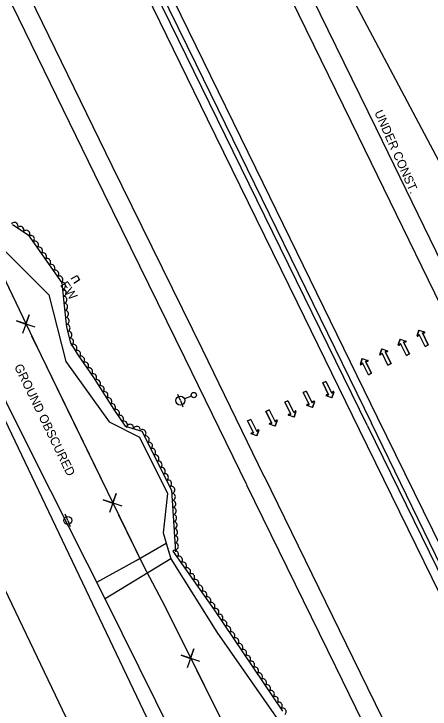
# Model space of a CAD drawing. Extents: x 1746719 to 1766531, y 631721 to 662391.
# Drawn here: x 1763435.4 to 1763670.9, y 634787.8 to 635180.8 of the extents above; entities that cross this region are included whole.
import ezdxf

# ---------------------------------------------------------------- set-up
doc = ezdxf.new("R2010")
doc.units = 0
for name, color, linetype in [('SURVEY - AERIAL SURVEY - Photo Control - Points - Elevations', 7, 'Continuous'), ('SURVEY - AERIAL SURVEY - Photo Control - Points - Locators', 7, 'Continuous'), ('SURVEY - AERIAL SURVEY - Photo Control - Points - Numbers', 7, 'Continuous'), ('SURVEY - AERIAL SURVEY - Photo Control with Text', 7, 'Continuous'), ('SURVEY - CENTERLINE - Existing Roads - Development', 7, 'Continuous'), ('SURVEY - CENTERLINE - Existing Roads Curve Text', 7, 'Continuous'), ('SURVEY - CENTERLINE - Existing Roads Text', 7, 'Continuous'), ('SURVEY - CENTERLINE - Preliminary - Development', 7, 'Continuous')]:
    doc.layers.add(name, color=color, linetype=linetype)

msp = doc.modelspace()

# ---------------------------------------------------------------- linework, layer by layer
at = {"layer": 'SURVEY - AERIAL SURVEY - Photo Control - Points - Elevations'}
for points in [[(1763704.89, 634983.66), (1763640.33, 635116.26), (1763572.67, 635254.52), (1763501.45, 635399.63), (1763427.19, 635551.31), (1763340.37, 635728.58), (1763263.89, 635885.41), (1763187.43, 636041.67), (1763122.68, 636173.79), (1763042.99, 636337.18), (1762975.48, 636475.16), (1762847.24, 636736.51)], [(1763695, 634978.85), (1763630.44, 635111.43), (1763562.79, 635249.68), (1763491.57, 635394.79), (1763417.31, 635546.47), (1763330.49, 635723.75), (1763254.01, 635880.59), (1763177.55, 636036.83), (1763112.8, 636168.96), (1763033.11, 636332.35), (1762965.6, 636470.32), (1762837.37, 636731.67)], [(1763641.05, 634952.58), (1763576.52, 635085.11), (1763508.91, 635223.28), (1763437.7, 635368.38), (1763363.42, 635520.08), (1763276.58, 635697.4), (1763200.09, 635854.25), (1763123.66, 636010.44), (1763058.89, 636142.6), (1762979.2, 636306.01), (1762911.72, 636443.92), (1762783.5, 636705.24)], [(1763021.68, 635785.45), (1763162.71, 635494.4), (1763322.79, 635171.93), (1763409.01, 634995.66), (1763533.5, 634734.93), (1763550.68, 634706.82), (1763569.17, 634679.56), (1763576.8, 634669.06), (1763621.03, 634611.29), (1763639.8, 634584.62), (1763657.35, 634557.11), (1763673.62, 634528.84), (1763683.42, 634510.24), (1763744.86, 634383.21), (1763804.27, 634250.31), (1763809.77, 634232.31), (1763813.73, 634213.9), (1763816.1, 634195.22), (1763816.89, 634176.41), (1763816.07, 634157.59), (1763813.68, 634138.91), (1763811.11, 634126.27), (1763784.4, 634012.32)], [(1763451.14, 635313.44), (1763490.95, 635231.84), (1763544.76, 635121.41), (1763595.76, 635017.71), (1763630.83, 634945.82)], [(1763397.21, 635287.13), (1763437.02, 635205.54), (1763490.87, 635095.03), (1763541.88, 634991.31), (1763576.91, 634919.51)], [(1763387.33, 635282.31), (1763427.14, 635200.72), (1763480.99, 635090.19), (1763532, 634986.47), (1763567.02, 634914.69)], [(1763469.18, 634774.33), (1763354.47, 635013.77)], [(1764286.91, 633632.22), (1764221.88, 633765.68), (1764141.2, 633930.05), (1764019.1, 634179.91), (1763913.63, 634395.49), (1763787.63, 634652.96), (1763703.71, 634825.14), (1763641.05, 634952.58)], [(1763630.83, 634945.82), (1763681.1, 634843.13), (1763756.43, 634688.91), (1763840.36, 634517.91), (1763911.67, 634371.12), (1763995.88, 634198.93), (1764084.74, 634017.62), (1764168.83, 633846.36), (1764236.28, 633708.97), (1764276.55, 633626.71)], [(1763576.94, 634919.44), (1763627.2, 634816.77), (1763702.54, 634662.52), (1763786.44, 634491.58), (1763857.74, 634344.83), (1763942, 634172.55), (1764030.87, 633991.19), (1764114.97, 633819.92), (1764182.41, 633682.55), (1764210.63, 633624.92)], [(1763567.06, 634914.6), (1763617.31, 634811.94), (1763692.66, 634657.68), (1763776.56, 634486.76), (1763847.85, 634340.01), (1763932.12, 634167.71), (1764021, 633986.35), (1764105.09, 633815.07), (1764172.53, 633677.71), (1764180.93, 633660.56)]]:
    msp.add_lwpolyline(points, dxfattribs=at)
at = {"layer": 'SURVEY - AERIAL SURVEY - Photo Control - Points - Locators'}
for p, q in [((1763663.51, 634998.86), (1763664.59, 635002.06)), ((1763664.59, 635002.06), (1763663.51, 634998.86)), ((1763664.59, 635002.06), (1763667.79, 635000.98)), ((1763664.59, 635002.06), (1763667.79, 635000.98)), ((1763664.74, 634999.54), (1763663.93, 634998.62)), ((1763664.74, 634999.54), (1763663.93, 634998.62)), ((1763668.08, 634992.81), (1763664.74, 634999.54)), ((1763668.08, 634992.81), (1763664.74, 634999.54)), ((1763667.73, 635000.5), (1763666.5, 635000.42)), ((1763666.5, 635000.42), (1763667.73, 635000.5)), ((1763666.5, 635000.42), (1763669.85, 634993.68)), ((1763669.85, 634993.68), (1763666.5, 635000.42)), ((1763652.89, 634993.75), (1763653.97, 634996.95)), ((1763653.97, 634996.95), (1763652.89, 634993.75)), ((1763654.12, 634994.43), (1763653.31, 634993.51)), ((1763654.12, 634994.43), (1763653.31, 634993.51)), ((1763653.97, 634996.95), (1763657.17, 634995.87)), ((1763653.97, 634996.95), (1763657.17, 634995.87)), ((1763657.47, 634987.7), (1763654.12, 634994.43)), ((1763657.47, 634987.7), (1763654.12, 634994.43)), ((1763657.11, 634995.39), (1763655.88, 634995.31)), ((1763655.88, 634995.31), (1763657.11, 634995.39)), ((1763655.88, 634995.31), (1763659.23, 634988.57)), ((1763659.23, 634988.57), (1763655.88, 634995.31)), ((1763642.46, 634988.26), (1763643.54, 634991.46)), ((1763643.54, 634991.46), (1763642.46, 634988.26)), ((1763643.54, 634991.46), (1763646.74, 634990.38)), ((1763643.54, 634991.46), (1763646.74, 634990.38)), ((1763646.68, 634989.9), (1763645.45, 634989.82)), ((1763645.45, 634989.82), (1763646.68, 634989.9)), ((1763669.85, 634993.68), (1763668.08, 634992.81)), ((1763668.08, 634992.81), (1763669.85, 634993.68)), ((1763631.43, 634982.79), (1763632.51, 634985.99)), ((1763632.51, 634985.99), (1763631.43, 634982.79)), ((1763632.51, 634985.99), (1763635.71, 634984.91)), ((1763632.51, 634985.99), (1763635.71, 634984.91)), ((1763643.69, 634988.94), (1763642.88, 634988.02)), ((1763643.69, 634988.94), (1763642.88, 634988.02)), ((1763647.03, 634982.21), (1763643.69, 634988.94)), ((1763647.03, 634982.21), (1763643.69, 634988.94)), ((1763645.45, 634989.82), (1763648.79, 634983.08)), ((1763648.79, 634983.08), (1763645.45, 634989.82)), ((1763659.23, 634988.57), (1763657.47, 634987.7)), ((1763657.47, 634987.7), (1763659.23, 634988.57)), ((1763632.66, 634983.48), (1763631.85, 634982.55)), ((1763632.66, 634983.48), (1763631.85, 634982.55)), ((1763636, 634976.74), (1763632.66, 634983.48)), ((1763636, 634976.74), (1763632.66, 634983.48)), ((1763635.65, 634984.44), (1763634.42, 634984.35)), ((1763634.42, 634984.35), (1763635.65, 634984.44)), ((1763634.42, 634984.35), (1763637.77, 634977.61)), ((1763637.77, 634977.61), (1763634.42, 634984.35)), ((1763648.79, 634983.08), (1763647.03, 634982.21)), ((1763647.03, 634982.21), (1763648.79, 634983.08)), ((1763637.77, 634977.61), (1763636, 634976.74)), ((1763636, 634976.74), (1763637.77, 634977.61)), ((1763610.12, 634972.19), (1763611.89, 634973.06)), ((1763611.89, 634973.06), (1763610.12, 634972.19)), ((1763613.47, 634965.45), (1763610.12, 634972.19)), ((1763610.12, 634972.19), (1763613.47, 634965.45)), ((1763611.89, 634973.06), (1763615.23, 634966.33)), ((1763611.89, 634973.06), (1763615.23, 634966.33)), ((1763599.09, 634966.72), (1763600.86, 634967.6)), ((1763600.86, 634967.6), (1763599.09, 634966.72)), ((1763602.44, 634959.98), (1763599.09, 634966.72)), ((1763599.09, 634966.72), (1763602.44, 634959.98)), ((1763600.86, 634967.6), (1763604.2, 634960.86)), ((1763600.86, 634967.6), (1763604.2, 634960.86)), ((1763615.23, 634966.33), (1763616.04, 634967.25)), ((1763615.23, 634966.33), (1763616.04, 634967.25)), ((1763616.46, 634967.01), (1763615.38, 634963.81)), ((1763615.38, 634963.81), (1763616.46, 634967.01)), ((1763615.38, 634963.81), (1763612.18, 634964.89)), ((1763615.38, 634963.81), (1763612.18, 634964.89)), ((1763612.24, 634965.37), (1763613.47, 634965.45)), ((1763613.47, 634965.45), (1763612.24, 634965.37)), ((1763588.66, 634961.23), (1763590.42, 634962.1)), ((1763590.42, 634962.1), (1763588.66, 634961.23)), ((1763592.01, 634954.49), (1763588.66, 634961.23)), ((1763588.66, 634961.23), (1763592.01, 634954.49)), ((1763590.42, 634962.1), (1763593.77, 634955.37)), ((1763590.42, 634962.1), (1763593.77, 634955.37)), ((1763604.35, 634958.34), (1763601.15, 634959.42)), ((1763604.35, 634958.34), (1763601.15, 634959.42)), ((1763601.21, 634959.9), (1763602.44, 634959.98)), ((1763602.44, 634959.98), (1763601.21, 634959.9)), ((1763604.2, 634960.86), (1763605.01, 634961.79)), ((1763604.2, 634960.86), (1763605.01, 634961.79)), ((1763605.43, 634961.55), (1763604.35, 634958.34)), ((1763604.35, 634958.34), (1763605.43, 634961.55)), ((1763578.04, 634956.12), (1763579.8, 634957)), ((1763579.8, 634957), (1763578.04, 634956.12)), ((1763581.39, 634949.38), (1763578.04, 634956.12)), ((1763578.04, 634956.12), (1763581.39, 634949.38)), ((1763579.8, 634957), (1763583.15, 634950.26)), ((1763579.8, 634957), (1763583.15, 634950.26)), ((1763593.77, 634955.37), (1763594.58, 634956.3)), ((1763593.77, 634955.37), (1763594.58, 634956.3)), ((1763595, 634956.06), (1763593.92, 634952.85)), ((1763593.92, 634952.85), (1763595, 634956.06)), ((1763567.68, 634950.66), (1763569.44, 634951.53)), ((1763569.44, 634951.53), (1763567.68, 634950.66)), ((1763571.02, 634943.92), (1763567.68, 634950.66)), ((1763567.68, 634950.66), (1763571.02, 634943.92)), ((1763569.44, 634951.53), (1763572.79, 634944.8)), ((1763569.44, 634951.53), (1763572.79, 634944.8)), ((1763583.15, 634950.26), (1763583.96, 634951.19)), ((1763583.15, 634950.26), (1763583.96, 634951.19)), ((1763584.38, 634950.95), (1763583.3, 634947.74)), ((1763583.3, 634947.74), (1763584.38, 634950.95)), ((1763593.92, 634952.85), (1763590.72, 634953.93)), ((1763593.92, 634952.85), (1763590.72, 634953.93)), ((1763590.78, 634954.41), (1763592.01, 634954.49)), ((1763592.01, 634954.49), (1763590.78, 634954.41)), ((1763583.3, 634947.74), (1763580.1, 634948.82)), ((1763583.3, 634947.74), (1763580.1, 634948.82)), ((1763580.16, 634949.3), (1763581.39, 634949.38)), ((1763581.39, 634949.38), (1763580.16, 634949.3)), ((1763572.94, 634942.28), (1763569.74, 634943.36)), ((1763572.94, 634942.28), (1763569.74, 634943.36)), ((1763569.8, 634943.83), (1763571.02, 634943.92)), ((1763571.02, 634943.92), (1763569.8, 634943.83)), ((1763572.79, 634944.8), (1763573.59, 634945.72)), ((1763572.79, 634944.8), (1763573.59, 634945.72)), ((1763574.01, 634945.48), (1763572.94, 634942.28)), ((1763572.94, 634942.28), (1763574.01, 634945.48))]:
    msp.add_line(p, q, dxfattribs=at)
for points in [[(1763548.12, 635593.75), (1763602.09, 635502.11), (1763634.72, 635435.11), (1763654.54, 635394.31), (1763687.84, 635325.87), (1763724.41, 635250.07), (1763755.64, 635177.54), (1763807.05, 635059.35), (1763784.48, 635044.83), (1763718.75, 635002.85), (1763677.55, 635094.54), (1763623.88, 635195.58), (1763597, 635259.5), (1763593.85, 635330.55), (1763534.99, 635419.78), (1763534.47, 635448.54), (1763499.23, 635506.99)], [(1763429.1, 635047.98), (1763455.2, 635021.94), (1763464.78, 634984.23), (1763489.38, 634950.16), (1763506.4, 634941.5), (1763522.31, 634909.72), (1763519.95, 634887.34), (1763524.14, 634872.81), (1763487.1, 634850.18), (1763446.17, 634931.23), (1763400.83, 635021.81)], [(1763482.33, 634859.53), (1763504.54, 634871.82), (1763521.62, 634881.62), (1763524.14, 634872.81), (1763550.27, 634831.33), (1763583.86, 634783.29)], [(1763534.96, 634753.47), (1763487.1, 634850.18), (1763482.33, 634859.53)]]:
    msp.add_lwpolyline(points, dxfattribs=at)
for centre, start, end in [((1763663.75, 634998.78), 161.4112, 318.9044), ((1763663.75, 634998.78), 161.4112, 318.9044), ((1763667.71, 635000.75), 273.9629, 71.4112), ((1763667.71, 635000.75), 273.9629, 71.4112), ((1763657.09, 634995.64), 273.9629, 71.4112), ((1763657.09, 634995.64), 273.9629, 71.4112), ((1763646.66, 634990.15), 273.9629, 71.4112), ((1763646.66, 634990.15), 273.9629, 71.4112), ((1763653.13, 634993.67), 161.4112, 318.9044), ((1763653.13, 634993.67), 161.4112, 318.9044), ((1763642.69, 634988.18), 161.4112, 318.9044), ((1763642.69, 634988.18), 161.4112, 318.9044), ((1763631.66, 634982.71), 161.4112, 318.9044), ((1763631.66, 634982.71), 161.4112, 318.9044), ((1763635.63, 634984.68), 273.9629, 71.4112), ((1763635.63, 634984.68), 273.9629, 71.4112), ((1763616.22, 634967.09), 341.4112, 138.9044), ((1763616.22, 634967.09), 341.4112, 138.9044), ((1763612.26, 634965.12), 93.9629, 251.4112), ((1763612.26, 634965.12), 93.9629, 251.4112), ((1763601.23, 634959.65), 93.9629, 251.4112), ((1763601.23, 634959.65), 93.9629, 251.4112), ((1763605.19, 634961.62), 341.4112, 138.9044), ((1763605.19, 634961.62), 341.4112, 138.9044), ((1763594.76, 634956.13), 341.4112, 138.9044), ((1763594.76, 634956.13), 341.4112, 138.9044), ((1763584.14, 634951.03), 341.4112, 138.9044), ((1763584.14, 634951.03), 341.4112, 138.9044), ((1763590.8, 634954.16), 93.9629, 251.4112), ((1763590.8, 634954.16), 93.9629, 251.4112), ((1763580.18, 634949.06), 93.9629, 251.4112), ((1763580.18, 634949.06), 93.9629, 251.4112), ((1763569.81, 634943.59), 93.9629, 251.4112), ((1763569.81, 634943.59), 93.9629, 251.4112), ((1763573.78, 634945.56), 341.4112, 138.9044), ((1763573.78, 634945.56), 341.4112, 138.9044)]:
    msp.add_arc(centre, 0.246, start, end, dxfattribs=at)
at = {"layer": 'SURVEY - AERIAL SURVEY - Photo Control - Points - Numbers'}
for points in [[(1763635.49, 634947.88), (1763550.57, 635121.13), (1763412.96, 635402), (1763296.92, 635639.14), (1763179.78, 635878.6), (1763016.73, 636211.43), (1762900.31, 636449.87), (1762810.07, 636633.97), (1762777.65, 636700.23)], [(1762780.33, 636702.09), (1762833.11, 636593.25), (1762910.17, 636436.51), (1763005.6, 636241.46), (1763118.37, 636010.26), (1763219.08, 635804.06), (1763329.74, 635578.22), (1763441.15, 635350.94), (1763538.42, 635152.66), (1763637.77, 634949.46)], [(1763635.49, 634947.88), (1763696.6, 634823.22), (1763800.9, 634609.62), (1763896.95, 634413.45), (1764004.19, 634194.3), (1764106.63, 633984.76), (1764197.37, 633799.63), (1764281.43, 633628.12)], [(1764283.41, 633629.46), (1764202.99, 633793.6), (1764120.58, 633962.6), (1764047.91, 634111.29), (1763960.25, 634289.05), (1763909.33, 634393.41), (1763836.64, 634541.81), (1763766.39, 634685.66), (1763677.3, 634867.98), (1763637.77, 634949.46)]]:
    msp.add_lwpolyline(points, dxfattribs=at)
at = {"layer": 'SURVEY - AERIAL SURVEY - Photo Control with Text'}
for points in [[(1763434.63, 635061.82), (1763443.54, 635055.84), (1763456.32, 635037.72), (1763462.59, 635028.74), (1763463.92, 635015.81), (1763465.22, 635003.79), (1763467.53, 634994.78), (1763471.25, 634988.58), (1763480.4, 634975.34), (1763491.9, 634957.14), (1763498.36, 634947.79), (1763507.8, 634944.83), (1763524.67, 634911.57), (1763526.79, 634876.62)], [(1763525.43, 634877.13), (1763548.79, 634843.83), (1763587.36, 634786.68)]]:
    msp.add_lwpolyline(points, dxfattribs=at)
for centre, major_axis in [((1763435.82, 635061.02), (1.66, -1.11)), ((1763439.14, 635058.79), (1.66, -1.11)), ((1763442.46, 635056.56), (1.66, -1.11)), ((1763445.1, 635053.63), (1.15, -1.63)), ((1763447.4, 635050.36), (1.15, -1.63)), ((1763449.71, 635047.09), (1.15, -1.63)), ((1763452.01, 635043.82), (1.15, -1.63)), ((1763454.32, 635040.55), (1.15, -1.63)), ((1763456.62, 635037.28), (1.14, -1.64)), ((1763458.91, 635034), (1.14, -1.64)), ((1763461.2, 635030.72), (1.14, -1.64)), ((1763462.75, 635027.17), (0.2, -1.99)), ((1763463.16, 635023.19), (0.2, -1.99)), ((1763463.57, 635019.21), (0.2, -1.99)), ((1763463.98, 635015.23), (0.22, -1.99)), ((1763464.41, 635011.25), (0.22, -1.99)), ((1763464.84, 635007.28), (0.22, -1.99)), ((1763465.34, 635003.31), (0.5, -1.94)), ((1763466.33, 634999.44), (0.5, -1.94)), ((1763467.33, 634995.56), (0.5, -1.94)), ((1763469.17, 634992.04), (1.03, -1.72)), ((1763471.23, 634988.61), (1.03, -1.72)), ((1763473.5, 634985.32), (1.14, -1.65)), ((1763475.77, 634982.03), (1.14, -1.65)), ((1763478.05, 634978.74), (1.14, -1.65)), ((1763480.32, 634975.45), (1.14, -1.65)), ((1763482.46, 634972.07), (1.07, -1.69)), ((1763484.6, 634968.69), (1.07, -1.69)), ((1763486.74, 634965.31), (1.07, -1.69)), ((1763488.87, 634961.93), (1.07, -1.69)), ((1763491.01, 634958.54), (1.07, -1.69)), ((1763493.23, 634955.22), (1.14, -1.65)), ((1763495.5, 634951.93), (1.14, -1.65)), ((1763497.77, 634948.64), (1.14, -1.65)), ((1763501.19, 634946.9), (1.91, -0.6)), ((1763505.01, 634945.7), (1.91, -0.6)), ((1763508.29, 634943.87), (0.9, -1.78)), ((1763510.1, 634940.3), (0.9, -1.78)), ((1763511.91, 634936.73), (0.9, -1.78)), ((1763513.72, 634933.16), (0.9, -1.78)), ((1763515.53, 634929.6), (0.9, -1.78)), ((1763517.33, 634926.03), (0.9, -1.78)), ((1763519.14, 634922.46), (0.9, -1.78)), ((1763520.95, 634918.89), (0.9, -1.78)), ((1763522.76, 634915.33), (0.9, -1.78)), ((1763524.57, 634911.76), (0.9, -1.78)), ((1763524.9, 634907.79), (0.12, -2)), ((1763525.14, 634903.8), (0.12, -2)), ((1763525.38, 634899.8), (0.12, -2)), ((1763525.62, 634895.81), (0.12, -2)), ((1763525.87, 634891.82), (0.12, -2)), ((1763526.11, 634887.83), (0.12, -2)), ((1763526.35, 634883.83), (0.12, -2)), ((1763526.59, 634879.84), (0.12, -2)), ((1763526.58, 634875.49), (1.15, -1.64)), ((1763528.87, 634872.22), (1.15, -1.64)), ((1763531.17, 634868.94), (1.15, -1.64)), ((1763533.47, 634865.67), (1.15, -1.64)), ((1763535.77, 634862.4), (1.15, -1.64)), ((1763538.06, 634859.12), (1.15, -1.64)), ((1763540.36, 634855.85), (1.15, -1.64)), ((1763542.66, 634852.57), (1.15, -1.64)), ((1763544.96, 634849.3), (1.15, -1.64)), ((1763547.25, 634846.02), (1.15, -1.64)), ((1763549.53, 634842.74), (1.12, -1.66)), ((1763551.77, 634839.42), (1.12, -1.66)), ((1763554.01, 634836.11), (1.12, -1.66)), ((1763556.25, 634832.79), (1.12, -1.66)), ((1763558.48, 634829.47), (1.12, -1.66)), ((1763560.72, 634826.16), (1.12, -1.66)), ((1763562.96, 634822.84), (1.12, -1.66)), ((1763565.2, 634819.53), (1.12, -1.66)), ((1763567.43, 634816.21), (1.12, -1.66)), ((1763569.67, 634812.9), (1.12, -1.66)), ((1763571.91, 634809.58), (1.12, -1.66)), ((1763574.15, 634806.26), (1.12, -1.66)), ((1763576.38, 634802.95), (1.12, -1.66)), ((1763578.62, 634799.63), (1.12, -1.66)), ((1763580.86, 634796.32), (1.12, -1.66)), ((1763583.1, 634793), (1.12, -1.66)), ((1763585.33, 634789.69), (1.12, -1.66)), ((1763587.57, 634786.37), (1.1, -1.67))]:
    msp.add_ellipse(centre, major_axis=major_axis, ratio=0.940188, start_param=0, end_param=3.141593, dxfattribs=at)
at = {"layer": 'SURVEY - CENTERLINE - Existing Roads - Development'}
for p, q in [((1763529.6, 634962.19), (1763528.19, 634965.66)), ((1763535.85, 634964.74), (1763531.92, 634963.13)), ((1763529.6, 634962.19), (1763531.02, 634958.71)), ((1763465.87, 634894.47), (1763464.37, 634897.91)), ((1763465.87, 634894.47), (1763467.36, 634891.03))]:
    msp.add_line(p, q, dxfattribs=at)
for centre, radius in [((1763537.24, 634965.3), 1.5), ((1763529.6, 634962.19), 2.5), ((1763465.87, 634894.47), 2.25)]:
    msp.add_circle(centre, radius, dxfattribs=at)
at = {"layer": 'SURVEY - CENTERLINE - Existing Roads Curve Text'}
for points in [[(1762923.24, 636069.27), (1762957.11, 636000.16), (1763028.37, 635856.25), (1763111.26, 635685.64), (1763194.35, 635513.86), (1763262.7, 635375.98), (1763309.84, 635279.41), (1763375.45, 635145.07), (1763450.62, 634988.03), (1763508.77, 634868.73)], [(1763416.94, 635058.4), (1763438.53, 635013.3)], [(1763447.48, 635003.62), (1763436.86, 635007.29), (1763442.19, 635005.41), (1763444.07, 635010.74), (1763440.27, 635000.16)], [(1763445.48, 634998.78), (1763450.62, 634988.03), (1763465.73, 634957.03)], [(1763465.73, 634957.03), (1763487.64, 634912.08)], [(1763496.67, 634902.47), (1763486.01, 634906.06), (1763491.36, 634904.22), (1763493.2, 634909.57), (1763489.47, 634898.96)], [(1763494.69, 634897.61), (1763508.77, 634868.73)], [(1763508.77, 634868.73), (1763520.75, 634845.87), (1763565.71, 634755.82), (1763603.49, 634683.47), (1763644.49, 634604.08), (1763659.64, 634574.81), (1763678.16, 634531.18), (1763710.08, 634457.23), (1763769.3, 634336.43), (1763810.78, 634252.62), (1763882.7, 634106.42), (1763935.12, 634000.2), (1764002.98, 633861.72), (1764062.82, 633739.38), (1764100.31, 633662.65), (1764130.81, 633600.06), (1764157.08, 633546.35)], [(1763508.77, 634868.73), (1763520.75, 634845.87), (1763531.55, 634824.22)], [(1763540.67, 634814.7), (1763529.99, 634818.19), (1763535.35, 634816.4), (1763537.14, 634821.76), (1763533.52, 634811.12)], [(1763538.75, 634809.82), (1763559.48, 634768.31)]]:
    msp.add_lwpolyline(points, dxfattribs=at)
at = {"layer": 'SURVEY - CENTERLINE - Existing Roads Text'}
msp.add_lwpolyline([(1763467.93, 635031.12), (1763471.23, 635032.88), (1763472.58, 635030.39), (1763469.31, 635028.41)], dxfattribs=at)

# ---------------------------------------------------------------- texts
at = {"layer": 'SURVEY - AERIAL SURVEY - Photo Control - Points - Locators'}
for s, rotation, p in [('UNDER CONST.', 293.9966, (1763639.24, 635125.12)), ('GROUND OBSCURED', 295.9154, (1763435.48, 634981.44))]:
    msp.add_text(s, height=5, rotation=rotation, dxfattribs=at).set_placement(p)
at = {"layer": 'SURVEY - CENTERLINE - Preliminary - Development'}
msp.add_text('EW', height=5, rotation=304.662, dxfattribs=at).set_placement((1763461.41, 635027.49))

doc.saveas('drawing.dxf')
